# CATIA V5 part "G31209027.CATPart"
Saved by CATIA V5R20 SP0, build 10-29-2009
Part number: G31209027
Revision: 10
Definition: design
Nomenclature: G31209027
Source: made
Description: NOT SPECIFIED
Bounding box of the stored display mesh (mm): x -5 to 27, y -8 to 8, z -8 to 8
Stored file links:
  C:\Users\Raffaele\Desktop\3D X SITO CF\BOLEX\23-BUSH REF 312\G31209027.CATPart

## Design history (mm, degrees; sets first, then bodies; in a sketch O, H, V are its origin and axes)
Body1 "MANIFOLD_SOLID_BREP #7395" (main body)
  Solid1: solid without history
Body2 "MANIFOLD_SOLID_BREP #7538"
  Solid2: solid without history
Body3 "MANIFOLD_SOLID_BREP #7681"
  Solid3: solid without history
Body4 "MANIFOLD_SOLID_BREP #7824"
  Solid4: solid without history
Body5 "MANIFOLD_SOLID_BREP #7967"
  Solid5: solid without history
Body6 "MANIFOLD_SOLID_BREP #8110"
  Solid6: solid without history
Body7 "MANIFOLD_SOLID_BREP #8253"
  Solid7: solid without history
Body8 "MANIFOLD_SOLID_BREP #8398"
  Solid8: solid without history
Body9 "MANIFOLD_SOLID_BREP #8543"
  Solid9: solid without history
Body10 "MANIFOLD_SOLID_BREP #8688"
  Solid10: solid without history
Body11 "MANIFOLD_SOLID_BREP #8833"
  Solid11: solid without history
Body12 "MANIFOLD_SOLID_BREP #8976"
  Solid12: solid without history
Body13 "MANIFOLD_SOLID_BREP #9119"
  Solid13: solid without history
Body14 "MANIFOLD_SOLID_BREP #9264"
  Solid14: solid without history
Body15 "MANIFOLD_SOLID_BREP #9409"
  Solid15: solid without history
Body16 "MANIFOLD_SOLID_BREP #9554"
  Solid16: solid without history
Body17 "MANIFOLD_SOLID_BREP #9699"
  Solid17: solid without history
Body18 "MANIFOLD_SOLID_BREP #9844"
  Solid18: solid without history
Body19 "MANIFOLD_SOLID_BREP #9989"
  Solid19: solid without history
Body20 "MANIFOLD_SOLID_BREP #10134"
  Solid20: solid without history
Body21 "MANIFOLD_SOLID_BREP #10277"
  Solid21: solid without history
Body22 "MANIFOLD_SOLID_BREP #10420"
  Solid22: solid without history
Body23 "MANIFOLD_SOLID_BREP #10565"
  Solid23: solid without history
Body24 "MANIFOLD_SOLID_BREP #10710"
  Solid24: solid without history
Body25 "MANIFOLD_SOLID_BREP #10855"
  Solid25: solid without history
Body26 "MANIFOLD_SOLID_BREP #11000"
  Solid26: solid without history
Body27 "MANIFOLD_SOLID_BREP #11145"
  Solid27: solid without history
Body28 "MANIFOLD_SOLID_BREP #11288"
  Solid28: solid without history
Body29 "MANIFOLD_SOLID_BREP #11433"
  Solid29: solid without history
Body30 "MANIFOLD_SOLID_BREP #11578"
  Solid30: solid without history
Body31 "MANIFOLD_SOLID_BREP #11721"
  Solid31: solid without history
Body32 "MANIFOLD_SOLID_BREP #11866"
  Solid32: solid without history
Body33 "MANIFOLD_SOLID_BREP #12011"
  Solid33: solid without history
Body34 "MANIFOLD_SOLID_BREP #12154"
  Solid34: solid without history
Body35 "MANIFOLD_SOLID_BREP #12297"
  Solid35: solid without history
Body36 "MANIFOLD_SOLID_BREP #12440"
  Solid36: solid without history
Body37 "MANIFOLD_SOLID_BREP #12583"
  Solid37: solid without history
Body38 "MANIFOLD_SOLID_BREP #12728"
  Solid38: solid without history
Body39 "MANIFOLD_SOLID_BREP #12873"
  Solid39: solid without history
Body40 "MANIFOLD_SOLID_BREP #13018"
  Solid40: solid without history
Body41 "MANIFOLD_SOLID_BREP #13163"
  Solid41: solid without history
Body42 "MANIFOLD_SOLID_BREP #13308"
  Solid42: solid without history
Body43 "MANIFOLD_SOLID_BREP #13451"
  Solid43: solid without history
Body44 "MANIFOLD_SOLID_BREP #13596"
  Solid44: solid without history
Body45 "MANIFOLD_SOLID_BREP #13741"
  Solid45: solid without history
Body46 "MANIFOLD_SOLID_BREP #13884"
  Solid46: solid without history
Body47 "MANIFOLD_SOLID_BREP #14029"
  Solid47: solid without history
Body48 "MANIFOLD_SOLID_BREP #14174"
  Solid48: solid without history
Body49 "MANIFOLD_SOLID_BREP #14317"
  Solid49: solid without history
Body50 "MANIFOLD_SOLID_BREP #14460"
  Solid50: solid without history
Body51 "MANIFOLD_SOLID_BREP #14605"
  Solid51: solid without history
Body52 "MANIFOLD_SOLID_BREP #14750"
  Solid52: solid without history
Body53 "MANIFOLD_SOLID_BREP #14895"
  Solid53: solid without history
Body54 "MANIFOLD_SOLID_BREP #15040"
  Solid54: solid without history
Body55 "MANIFOLD_SOLID_BREP #15185"
  Solid55: solid without history
Body56 "MANIFOLD_SOLID_BREP #15328"
  Solid56: solid without history
Body57 "MANIFOLD_SOLID_BREP #15471"
  Solid57: solid without history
